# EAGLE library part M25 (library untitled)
SubD-Buchse korrigiert und verschönert Kantenmontage ReicheltD-SUB ST 250,14&euro;
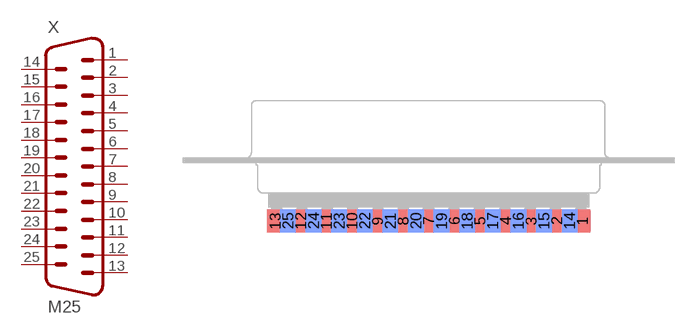
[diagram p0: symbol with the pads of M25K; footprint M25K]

Designator prefix X

## M25K  [M25K]
1  1  pas
2  2  pas
3  3  pas
4  4  pas
5  5  pas
6  6  pas
7  7  pas
8  8  pas
9  9  pas
10  10  pas
11  11  pas
12  12  pas
13  13  pas
14  14  pas
15  15  pas
16  16  pas
17  17  pas
18  18  pas
19  19  pas
20  20  pas
21  21  pas
22  22  pas
23  23  pas
24  24  pas
25  25  pas

## Footprint M25K (pad centres in mm)
SubD korrigiert, Pinabstand: 109 mil (nicht 108) Kantenmontage ReicheltD-SUB ST 250,14&euro; Kürzere Lötinseln - genügen! Ohne Lötpaste!
smd 1.7 x 2.5: 1 16.612,-1.75; 2 13.843,-1.75; 3 11.074,-1.75; 4 8.306,-1.75; 5 5.537,-1.75; 6 2.769,-1.75; 7 0,-1.75; 8 -2.769,-1.75; 9 -5.537,-1.75; 10 -8.306,-1.75; 11 -11.074,-1.75; 12 -13.843,-1.75; 13 -16.612,-1.75
smd 1.7 x 2.5 bottom: 14 15.227,-1.75; 15 12.459,-1.75; 16 9.69,-1.75; 17 6.921,-1.75; 18 4.153,-1.75; 19 1.384,-1.75; 20 -1.384,-1.75; 21 -4.153,-1.75; 22 -6.921,-1.75; 23 -9.69,-1.75; 24 -12.459,-1.75; 25 -15.227,-1.75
